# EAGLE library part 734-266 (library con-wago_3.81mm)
Serie 734, Stiftleiste (für Leiterplatten) Einlötstift abgewinkelt 1 x 1 mm / Series 734, Male header (for PCBs) Angled solder pin 1 x 1 mm Polzahl / Pole No.: 6 Rastermaß / Pitch: 3.81 mm Bemessungsspannung / Rated Voltage: 160 V Nennstrom / Nominal Current: 10 A Lötstiftlänge: / Solder Pin Length: 3.8 mm Farbe / Color: orange / orange Stand: 01.01.2012. Die jeweils aktuellen Daten zu diesem Artikel finden Sie in unserem Produktkatalog, den Sie unter www.wago.com einsehen können. As of: 01/01/2012. Please find the newest data for this article in our product catalogue, which can be viewed under www.wago.com.
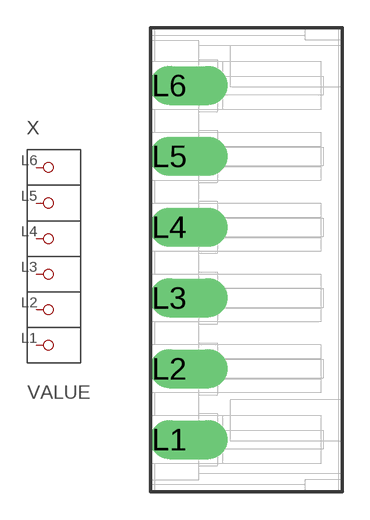
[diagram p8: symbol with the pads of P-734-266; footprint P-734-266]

Designator prefix X

## 734-266  [P-734-266]
L1  P1
L2  P2
L3  P3
L4  P4
L5  P5
L6  P6

## Footprint P-734-266 (pad centres in mm)
drill 1.4 pad 2 offset: L1 -4.15,-9.675; L2 -4.15,-5.865; L3 -4.15,-2.055; L4 -4.15,1.755; L5 -4.15,5.565; L6 -4.15,9.375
